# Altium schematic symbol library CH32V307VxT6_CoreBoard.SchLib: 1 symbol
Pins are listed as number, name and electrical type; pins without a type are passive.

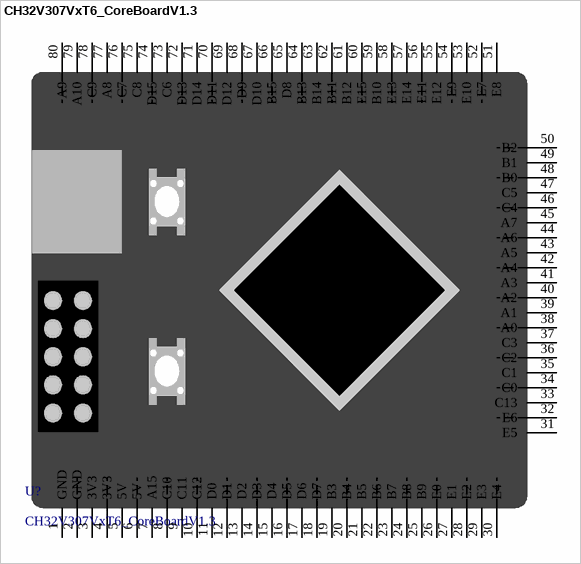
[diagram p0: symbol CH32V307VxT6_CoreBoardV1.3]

## CH32V307VxT6_CoreBoardV1.3
designator U?
footprint CH32V307VxT6_CoreBoard (逐飞科技CH32V307VxT6核心板)
pins: 1 GND, 2 GND, 3 3V3, 4 3V3, 5 5V, 6 5V, 7 A15, 8 C10, 9 C11, 10 C12, 11 D0, 12 D1, 13 D2, 14 D3, 15 D4, 16 D5, 17 D6, 18 D7, 19 B3, 20 B4, 21 B5, 22 B6, 23 B7, 24 B8, 25 B9, 26 E0, 27 E1, 28 E2, 29 E3, 30 E4, 31 E5, 32 E6, 33 C13, 34 C0, 35 C1, 36 C2, 37 C3, 38 A0, 39 A1, 40 A2, 41 A3, 42 A4, 43 A5, 44 A6, 45 A7, 46 C4, 47 C5, 48 B0, 49 B1, 50 B2, 51 E8, 52 E7, 53 E10, 54 E9, 55 E12, 56 E11, 57 E14, 58 E13, 59 B10, 60 E15, 61 B12, 62 B11, 63 B14, 64 B13, 65 D8, 66 B15, 67 D10, 68 D9, 69 D12, 70 D11, 71 D14, 72 D13, 73 C6, 74 D15, 75 C8, 76 C7, 77 A8, 78 C9, 79 A10, 80 A9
